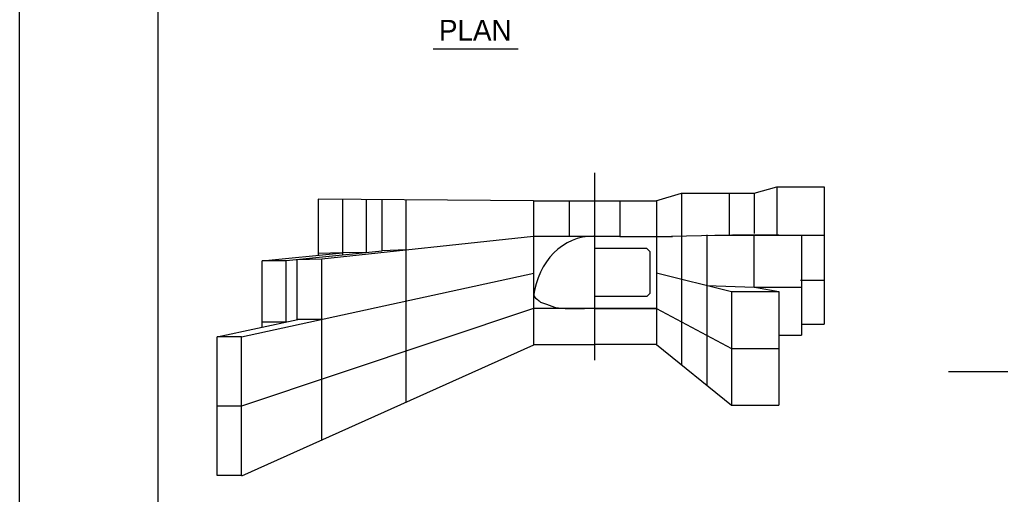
# Model space of a CAD drawing. Extents: x 593 to 1473, y 721 to 1315.
# Drawn here: x 592.7 to 875.7, y 975.5 to 1112.5 of the extents above; entities that cross this region are included whole.
import ezdxf

# ---------------------------------------------------------------- set-up
doc = ezdxf.new("R2010")
doc.units = 0
doc.layers.add('2', color=7, linetype='Continuous')
doc.layers.add('PLT-BNDY', color=7, linetype='Continuous')

msp = doc.modelspace()

# ---------------------------------------------------------------- linework, layer by layer
at = {"layer": '2'}
for p, q in [((632.66, 736.4), (632.66, 1300.4)), ((712.03, 1104.04), (736.53, 1104.04)), ((758.66, 1014.18), (758.66, 1068.26)), ((804.66, 1062.4), (811.16, 1064.18)), ((811.16, 1064.18), (824.78, 1064.18)), ((811.16, 1064.18), (811.16, 1050.31)), ((824.78, 1064.18), (824.78, 1024.54)), ((776.28, 1060.18), (783.66, 1062.4)), ((783.66, 1062.4), (783.66, 1012.82)), ((783.66, 1062.4), (804.66, 1062.4)), ((797.41, 1062.4), (797.41, 1050.31)), ((804.66, 1062.4), (804.66, 1050.77)), ((678.78, 1060.63), (678.78, 1044.44)), ((740.91, 1060.18), (678.84, 1060.63)), ((685.78, 1060.58), (685.78, 1044.59)), ((692.66, 1060.53), (692.66, 1045.29)), ((697.28, 1045.76), (697.28, 1060.5)), ((704.16, 1016.77), (704.16, 1060.45)), ((740.91, 1060.18), (740.91, 1029.06)), ((740.91, 1060.18), (740.91, 1028.81)), ((765.86, 1060.18), (776.28, 1060.18)), ((776.41, 1060.18), (776.41, 1029.06)), ((776.41, 1060.18), (776.41, 1029.06)), ((776.41, 1049.93), (798.03, 1050.38)), ((790.91, 1050.37), (790.91, 1006.95)), ((793.28, 1050.31), (818.28, 1050.31)), ((798.41, 1050.38), (811.78, 1050.38)), ((804.66, 1035.25), (804.66, 1050.31)), ((818.28, 1050.31), (818.28, 1021.37)), ((818.28, 1050.31), (824.87, 1050.31)), ((740.91, 1049.93), (679.91, 1043.38)), ((751.36, 1049.93), (740.91, 1049.93)), ((765.86, 1049.93), (776.41, 1049.93)), ((776.41, 1049.93), (781.03, 1049.93)), ((662.66, 1042.86), (685.78, 1045.13)), ((669.53, 1042.92), (697.28, 1045.76)), ((685.78, 1045.13), (678.78, 1045)), ((692.66, 1045.29), (685.78, 1045.13)), ((704.16, 1045.99), (697.28, 1045.76)), ((773.66, 1046.43), (758.66, 1046.43)), ((773.66, 1046.43), (774.53, 1045.56)), ((774.53, 1045.56), (774.53, 1033.43)), ((662.66, 1023.61), (662.66, 1042.86)), ((669.53, 1042.86), (662.66, 1042.86)), ((669.53, 1025.21), (669.53, 1042.86)), ((679.91, 1043.38), (672.78, 1043.18)), ((672.78, 1025.87), (672.78, 1043.18)), ((679.91, 1008.66), (679.91, 1043.38)), ((656.66, 1020.89), (741.03, 1039.31)), ((776.41, 1039.43), (798.03, 1033.98)), ((817.97, 1037.29), (824.78, 1037.29)), ((774.53, 1033.43), (773.66, 1032.56)), ((790.91, 1035.78), (804.66, 1035.25)), ((798.03, 1033.98), (798.03, 1001.18)), ((798.03, 1033.98), (811.78, 1033.98)), ((804.66, 1035.25), (818.28, 1035.25)), ((805.32, 1035.13), (811.78, 1033.98)), ((811.78, 1033.98), (811.78, 1001.18)), ((773.66, 1032.56), (758.66, 1032.56)), ((740.91, 1029.06), (656.66, 1000.89)), ((776.41, 1029.06), (740.91, 1029.06)), ((776.41, 1029.06), (798.03, 1017.58)), ((649.66, 1020.89), (672.9, 1025.9)), ((669.53, 1025.17), (662.66, 1025.17)), ((679.91, 1025.96), (672.78, 1025.96)), ((818.28, 1024.54), (824.78, 1024.54)), ((649.66, 1000.89), (649.66, 1020.89)), ((656.66, 1020.89), (649.66, 1020.89)), ((656.66, 1000.89), (656.66, 1020.89)), ((811.78, 1021.37), (818.28, 1021.37)), ((740.91, 1018.56), (656.66, 980.76)), ((704.16, 1002.07), (704.16, 1016.77)), ((776.41, 1018.68), (798.03, 1001.18)), ((798.03, 1017.58), (811.78, 1017.58)), ((860.7, 1010.96), (967.45, 1010.96)), ((679.91, 991.19), (679.91, 1008.66)), ((656.66, 1000.89), (649.66, 1000.89)), ((649.66, 980.89), (649.66, 1000.89)), ((656.66, 980.89), (656.66, 1000.89)), ((798.03, 1001.18), (811.78, 1001.18)), ((656.66, 980.89), (649.66, 980.89))]:
    msp.add_line(p, q, dxfattribs=at)
msp.add_lwpolyline([(740.91, 1060.18), (751.36, 1060.18)], dxfattribs=at)
for points in [[(765.86, 1060.18), (765.86, 1049.93), (751.36, 1049.93), (751.36, 1060.18)], [(740.91, 1029.06), (740.91, 1018.68), (758.66, 1018.68), (758.66, 1029.06)], [(776.41, 1029.06), (776.41, 1018.68), (758.66, 1018.68), (758.66, 1029.06)]]:
    msp.add_lwpolyline(points, close=True, dxfattribs=at)
msp.add_arc((742.56, 1033.16), 1.5, 158.6734, 246.8079, dxfattribs=at)
msp.add_ellipse((757.84, 1029.83), major_axis=(0, 20.11), ratio=0.847171, start_param=6.257419, end_param=7.719175, dxfattribs=at)
msp.add_spline([(742.03, 1031.81), (742.53, 1031.31), (744.66, 1030.31), (747.78, 1029.31), (749.28, 1029.18), (755.66, 1029.06)], degree=3, dxfattribs=at)
at = {"layer": 'PLT-BNDY'}
msp.add_lwpolyline([(592.66, 1315.4), (1433.66, 1315.4), (1433.66, 721.4), (592.66, 721.4)], close=True, dxfattribs=at)

# ---------------------------------------------------------------- texts
at = {"layer": '2'}
msp.add_text('PLAN', height=6, dxfattribs=at).set_placement((713.66, 1106.41))

doc.saveas('drawing.dxf')
